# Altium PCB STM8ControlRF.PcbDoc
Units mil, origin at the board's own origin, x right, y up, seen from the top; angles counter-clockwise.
Board outline 2025.03 x 1260.03 mil, 2 copper layers (Top Layer, Bottom Layer); 18 components, 22 nets, 93 pads, 0 vias.
Unrouted connection lines stored in the file: 3.
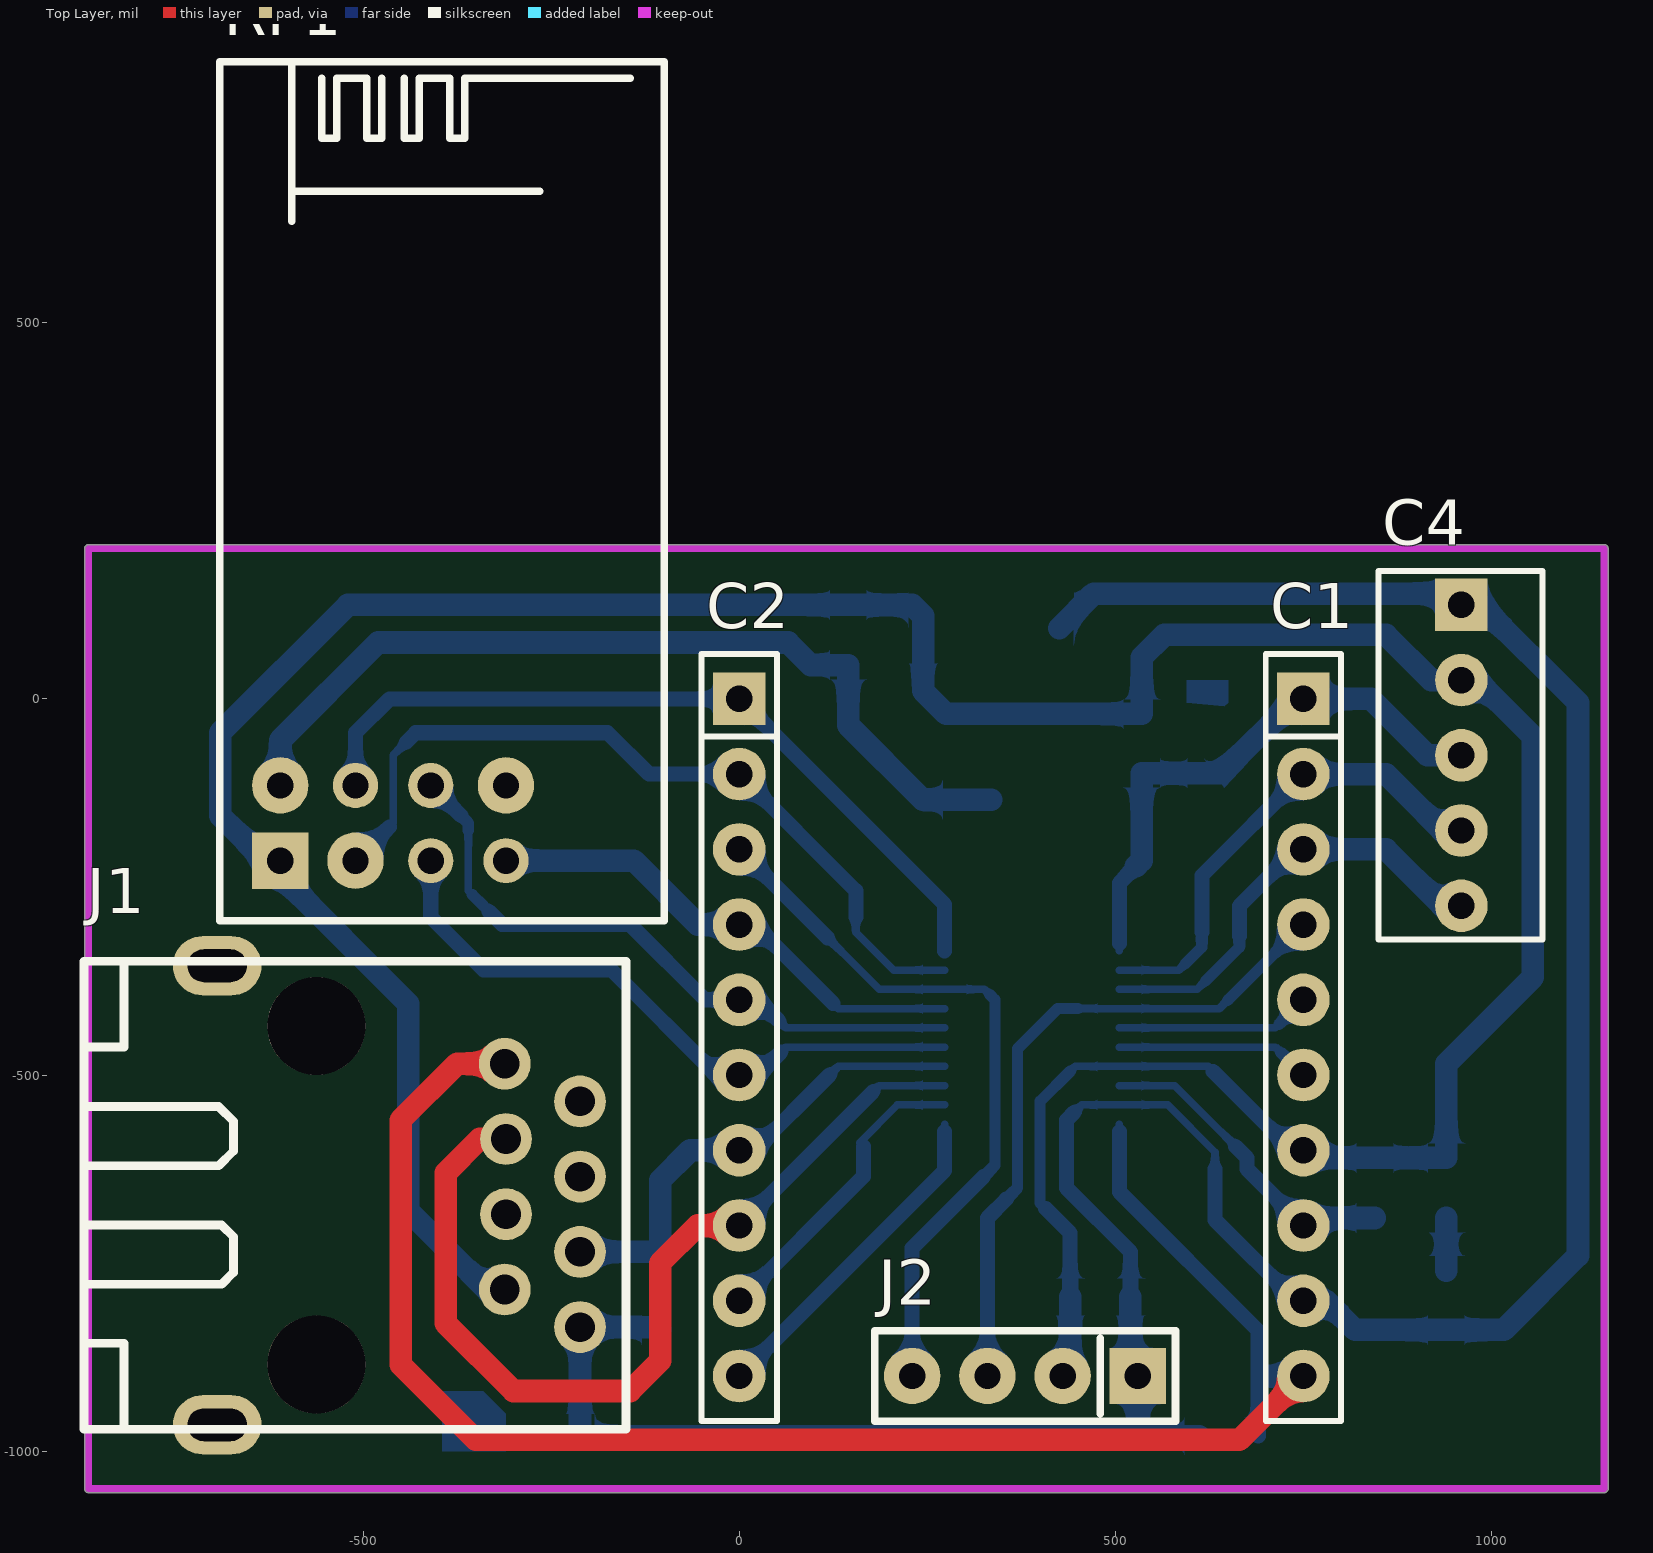
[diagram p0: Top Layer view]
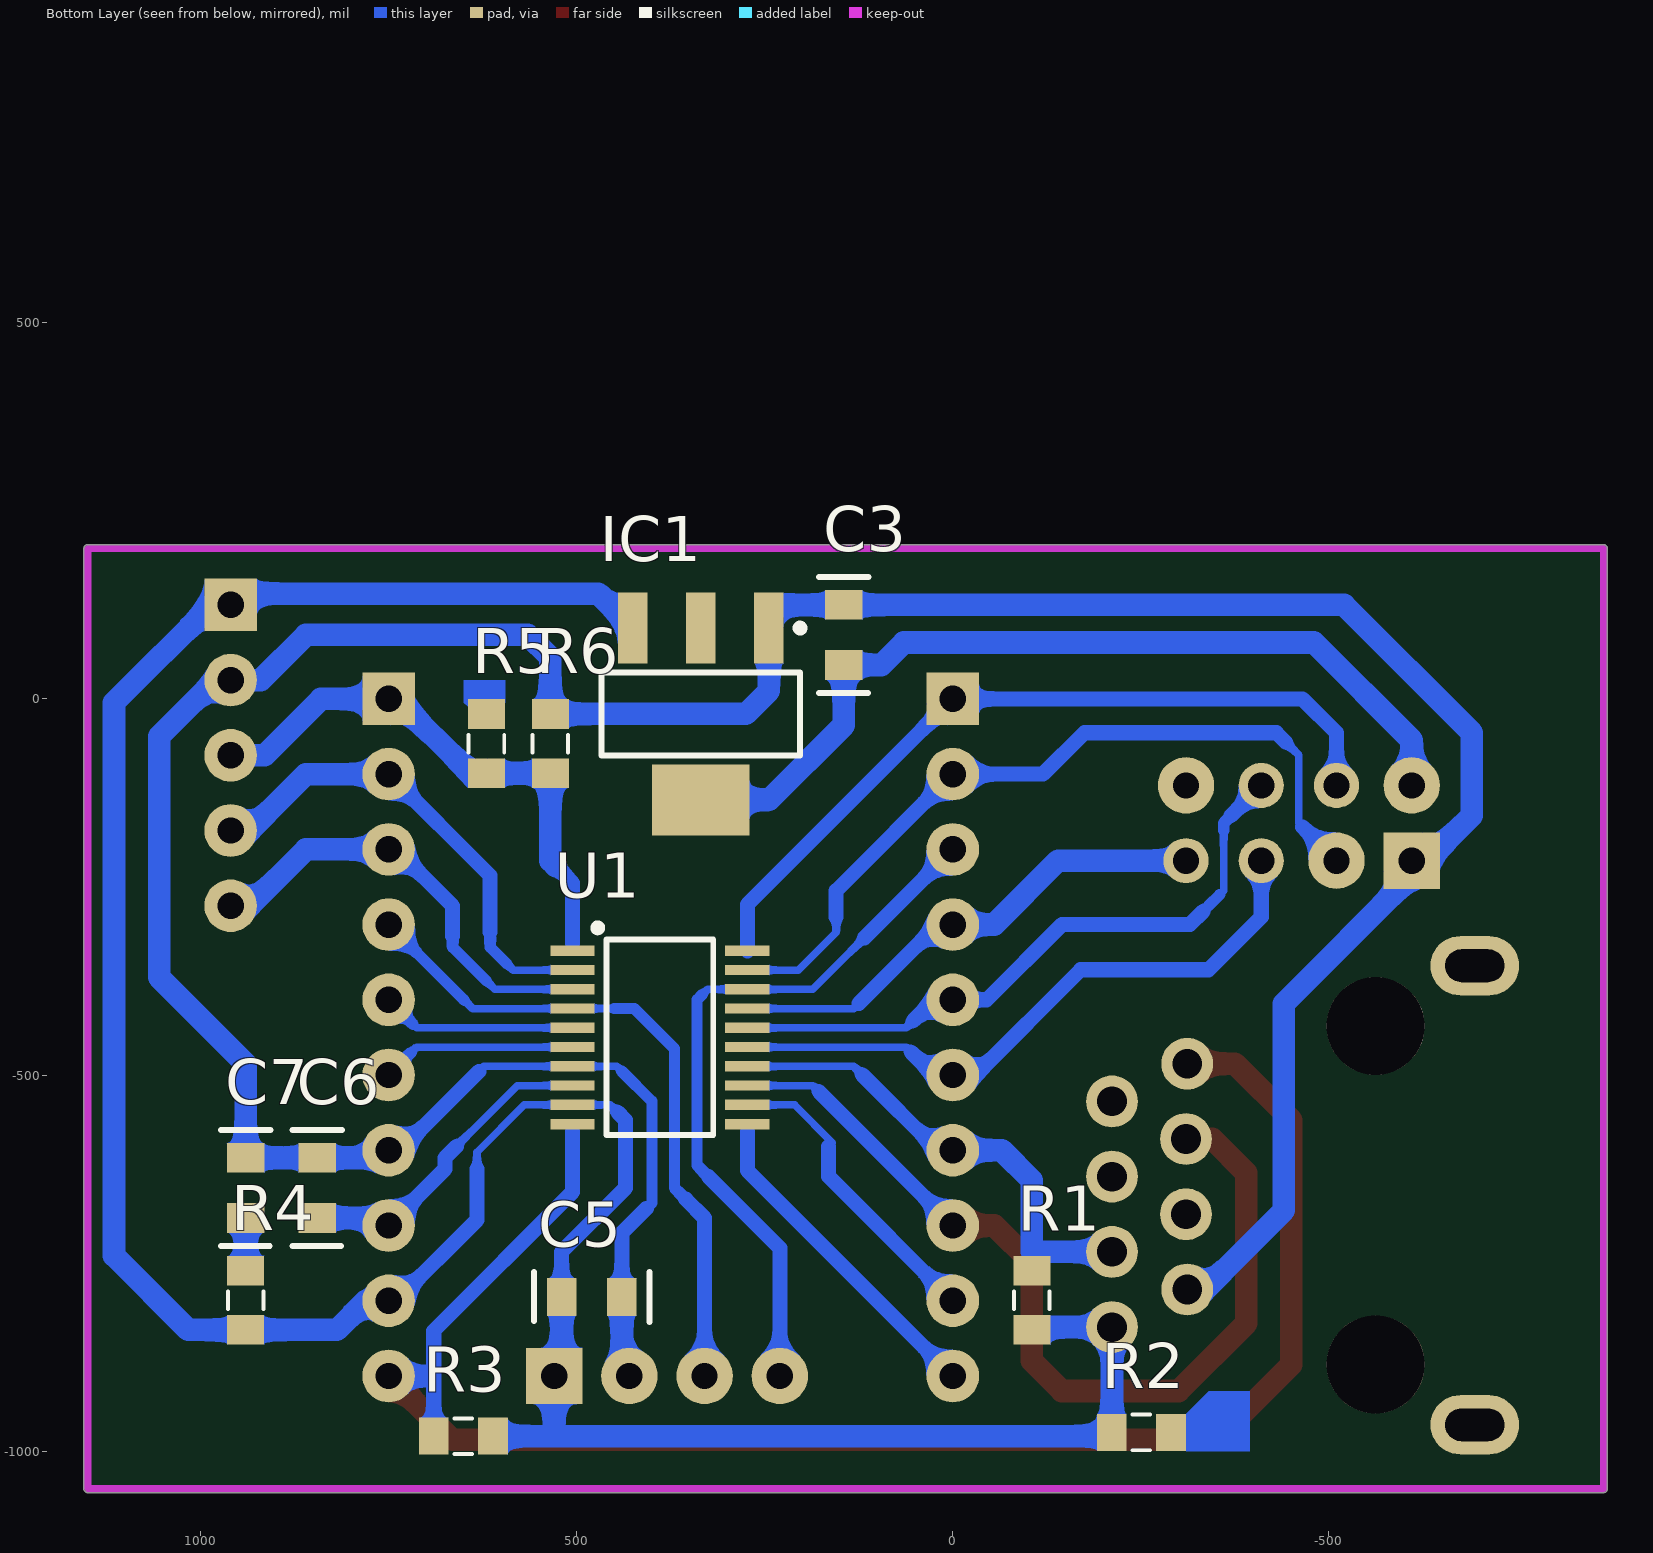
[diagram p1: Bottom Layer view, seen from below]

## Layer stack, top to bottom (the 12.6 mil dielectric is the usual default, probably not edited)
Top Solder: solder mask 0.4, Solder Resist, Dk 3.5
Top Layer: signal copper 1.4
Dielectric 1: dielectric 12.6, FR-4, Dk 4.8
Bottom Layer: signal copper 1.4
Bottom Solder: solder mask 0.4, Solder Resist, Dk 3.5

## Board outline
-865,-1055.01 cw(c-865,-1050) -870.02,-1050 -870.02,200 cw(c-865,200) -865,205.01 1150,205.01 cw(c1150,200) 1155.01,200 1155.01,-1050 cw(c1150,-1050) 1150,-1055.01

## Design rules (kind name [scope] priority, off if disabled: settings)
Clearance [All] p1: gap=10 ignorepadtopadclearanceinfootprint=FALSE except(0: Arc-Hole Track-Hole SMDPad-Hole THPad-Hole Via-Hole Fill-Hole Poly-Hole Region-Hole Text-Hole)
PolygonConnect [All] p1: connectstyle=Relief reliefconductorwidth=10 reliefentries=4 polygonreliefangle="90 Angle" airgapwidth=10
RoomDefinition STM8ControlRF [InComponentClass('STM8ControlRF')] p1: confinementstyle=ConfineIn formatcopy=TRUE lockcomponents=FALSE outline -2690,-3870 -690,-3870 -690,-2870 -2690,-2870
RoutingVias [All] p1: holewidth=28 width=50 viastyle="Through Hole" minholewidth=28 minwidth=50 maxholewidth=28 maxwidth=50
SolderMaskExpansion [All] p1: expansion=4
Width [All] p1: maxlimit=30 minlimit=10 preferedwidth=15
30 further rules are at their usual default settings.

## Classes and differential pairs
component class STM8ControlRF: C1 C2 C3 C4 C5 C6 C7 IC1 J1 J2 R1 R2 R4 R5 R6 RF1 U1

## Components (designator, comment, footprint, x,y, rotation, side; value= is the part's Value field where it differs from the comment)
C1 "JP10" JP10-C1T 750,0 r270 top
C2 "JP10" JP10-C1T 0,0 r270 top
C3 "104" C0805 145,85 r270 bottom value=33p
C4 "Header5" HDR5 960,125 r270 top
C5 "104" C0805 480,-795 r0 bottom value=33p
C6 "105" C0805 845,-650 r270 bottom value=33p
C7 "104" C0805 940,-650 r270 bottom value=33p
IC1 "AMS_1117" SOT_223_2 335,-20 r270 bottom
J1 "RJ45-12P" RJ45-8PIN_18MM_NO_TRANSFORMER -871.02,-659.8 r270 top
J2 "Jump_4" Jump_4 530,-900 r270 top
R1 "10K" RES-0805 -105,-760 r90 bottom value=1K
R2 "10K" RES-0805 -290,-975 r180 bottom value=1K
R3 "10K" RES-0805 690,-980 r0 bottom value=1K
R4 "10K" RES-0805 940,-760 r90 bottom value=1K
R5 "1K" RES-0805 620,-98.74 r270 bottom
R6 "2K" RES-0805 535,-20 r90 bottom value=1K
RF1 "RF24L01" RF24L01 -395,-95 r270 top
U1 "STM8S003F3P6" TSSOP20 389.37,-450 r180 bottom

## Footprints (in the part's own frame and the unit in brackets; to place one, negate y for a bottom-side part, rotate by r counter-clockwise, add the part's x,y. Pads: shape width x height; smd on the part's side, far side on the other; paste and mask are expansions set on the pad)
C0805 [mil] "Chip Resistor; Body 2.0 x 1.3 mm (LxW typ)"
  rect 39.37x50 smd: 1(-40,0) 2(40,0)
  silkscreen extent -77,-33 77,33, body extent -39,-25 39,25, height 31
HDR5 [mil] "Connector; Header; 5 Position"
  rect 70x70 hole 35: 1(0,0)
  round 70 hole 35: 2(100,0) 3(200,0) 4(300,0) 5(400,0)
  silkscreen extent -45,-110 445,108, body extent -50,-115 450,113, height 461
JP10-C1T [mil] "10 row, straight, gold plating"
  rect 70x70 hole 35: 1(0,0)
  round 70 hole 35: 2(100,0) 3(200,0) 4(300,0) 5(400,0) 6(500,0) 7(600,0) 8(700,0) 9(800,0) 10(900,0)
  silkscreen extent -60,-50 960,50, body extent -60,-49 960,49, height 335
Jump_4 [mil] "Jump_4 Pin 2.54"
  rect 75x75 hole 35: 1(0,0)
  round 75 hole 35: 2(0,-100) 3(0,-200) 4(0,-300)
  silkscreen extent -60,-350 60,50, body extent -53,-353 53,53, height 346
RES-0805 [mm] "Chip Resistor; Body 2 x 1.2 mm (LxW typ)"
  rect 1x1.25 smd: 1(0,0) 2(-2,0)
  silkscreen extent -1.3,-0.6 -0.7,0.6, body extent -2,-0.6 0,0.6, height 0.7
RF24L01 [mil] "Module RF24L01"
  rect 75x75 hole 35: 1(120,-215)
  round 75 hole 35: 2(20,-215) 3(120,-115) 8(20,85)
  round 60 hole 35: 4(20,-115) 5(120,-15) 6(20,-15) 7(120,85)
  silkscreen extent -942,-295 200,295, body extent -942,-300 200,290, height 138
RJ45-8PIN_18MM_NO_TRANSFORMER [mm]
  oval 2x3 hole 1.1 slot 2 at 90 deg mask+0: 0(-7.75,4.5) 0(7.75,4.5)
  round 3.3 hole 3.3 unplated mask+0: 0(-5.715,7.85) 0(5.715,7.85)
  round 1.75 hole 1: 1(-4.44,14.21) 2(-3.17,16.75) 3(-1.9,14.25) 4(-0.63,16.75) 5(0.64,14.25) 6(1.91,16.75) 7(3.18,14.21) 8(4.45,16.75)
  silkscreen extent -7.9,0 7.9,18.3, body extent -7.9,0 7.9,18.3, height 13.2
SOT_223_2 [mm] "SOT223, 4-Leads, Body 6.5x3.5mm, Pitch 2.3mm, Lead Span 7mm, IPC Medium Density"
  rect 2.4x1 smd: 1(-2.9,2.3) 2(-2.9,0) 3(-2.9,-2.3)
  rect 2.4x3.3 smd: 2(2.9,0)
  silkscreen extent -3.02,-3.35 1.4,3.47, body extent -3.39,-3.27 3.5,3.23, height 1.72
TSSOP20 [mm] "TSOP, 20-Leads, Body 6.5x4.4mm, Pitch 0.65mm, IPC Medium Density"
  rect 1.5x0.35 smd: 1(-2.95,2.925) 2(-2.95,2.275) 3(-2.95,1.625) 4(-2.95,0.975) 5(-2.95,0.325) 6(-2.95,-0.325) 7(-2.95,-0.975) 8(-2.95,-1.625) 9(-2.95,-2.275) 10(-2.95,-2.925) 11(2.95,-2.925) 12(2.95,-2.275) 13(2.95,-1.625) 14(2.95,-0.975) 15(2.95,-0.325) 16(2.95,0.325) 17(2.95,0.975) 18(2.95,1.625) 19(2.95,2.275) 20(2.95,2.925)
  silkscreen extent -2.23,-3.3 1.8,3.82, body extent -3.2,-3.25 3.2,3.25, height 1.2

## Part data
C1 C2: "WR-PHD 2.54 mm Angled Socket Header", Manufacturer="Würth Elektronik eiSos GmbH", partNo=613010143121
C3 C5 C6 C7: library part CapSMD, "Capacitor"
C4: "Header IDC, 5 x 1 Pin Vertical 2.54mm Pitch (Non-Boxed, Male)", Manufacturer="Würth Elektronik eiSos GmbH", partNo=613002143121
IC1: "IC Power"
J1: library part RJ45-12PIN_NO_TRANSFORMER
R1 R2 R3 R4 R5 R6: library part RES, "Resistor SMD"
RF1: "Module RF24L01"

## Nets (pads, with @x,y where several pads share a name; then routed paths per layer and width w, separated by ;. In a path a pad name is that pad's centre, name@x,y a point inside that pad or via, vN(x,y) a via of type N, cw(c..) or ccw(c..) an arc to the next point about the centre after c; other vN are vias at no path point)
1: C1.1 C4.3 R5.1 R6.2 U1.1 | length 745.3
  Bottom Layer w10: U1.1 505.51,-325
  Bottom Layer w20: 505.51,-325 505.51,-244.49 527.5,-222.5
  Bottom Layer w30: 527.5,-222.5 535,-215 R6.2 R5.1 641.26,-98.74 740,0 C1.1 840,0 915,-75 C4.3
2: C1.2 C4.4 U1.2 | length 649.1
  Bottom Layer w10: U1.2 584.57,-360.43 592.5,-352.5
  Bottom Layer w15: 592.5,-352.5 615,-330 615,-310
  Bottom Layer w20: 615,-310 615,-235 C1.2
  Bottom Layer w30: C1.2 860,-100 935,-175 C4.4
3: C1.3 C4.5 U1.3 | length 594.8
  Bottom Layer w10: U1.3 608.98,-386.02 620,-375
  Bottom Layer w15: 620,-375 665,-330 665,-315
  Bottom Layer w20: 665,-315 665,-275 740,-200 C1.3
  Bottom Layer w30: C1.3 860,-200 935,-275 C4.5
4: C1.4 J2.3 U1.4 | length 899.9
  Bottom Layer w10: 450,-411.61 U1.4 638.39,-411.61 650,-400
  Bottom Layer w15: 355,-665 370,-650 370,-465 423.39,-411.61 450,-411.61 ; 650,-400 C1.4
  Bottom Layer w20: J2.3 330,-690 355,-665
5: C1.5 U1.5 | length 259.9
  Bottom Layer w10: U1.5 712.8,-437.2 717.5,-432.5
  Bottom Layer w15: 717.5,-432.5 C1.5
6: C1.6 U1.6 | length 259.9
  Bottom Layer w10: U1.6 712.8,-462.8 720,-470
  Bottom Layer w15: 720,-470 C1.6
7: C1.7 C3.1 C4.2 C5.1 C6.1 C7.1 IC1.1 J1.7 J2.2 R6.1 RF1.1 U1.7 | length 4602.6
  Bottom Layer w10: 440,-495 446.61,-488.39 U1.7 623.39,-488.39 630,-495
  Bottom Layer w15: 407.5,-677.5 400,-670 400,-535 440,-495
  Bottom Layer w20: 407.5,-677.5 440,-710 C5.1 ; 630,-495 735,-600 C1.7
  Bottom Layer w30: J1.7 -335,-785 -440,-680 -440,-405 -610,-235 RF1.1 -630,-215 -690,-155 -690,-45 -520,125 C3.1 230,125 244.45,110.55 IC1.1 244.45,10.55 275,-20 R6.1 535,55 565,85 860,85 920,25 C4.2 980,25 1055,-50 1055,-370 940,-485 C7.1 C6.1 760,-610 C1.7 ; J2.2 440,-890 C5.1
8: C1.8 C6.2 U1.8 | length 429.5
  Bottom Layer w10: U1.8 578.98,-513.98 660,-595
  Bottom Layer w20: 660,-595 675,-610 675,-625 C1.8
  Bottom Layer w30: C1.8 760,-690 C6.2
10: C1.10 J1.1 R3.1 U1.10 | length 2317.4
  Top Layer w30: J1.1 -375,-485 -450,-560 -450,-885 -350,-985 665,-985 C1.10
  Bottom Layer w10: 505.51,-575 U1.10
  Bottom Layer w20: 505.51,-575 505.51,-655.51 690,-840 R3.1
  Bottom Layer w30: 695,-900 C1.10
11: C2.10 U1.11 | length 455.1
  Bottom Layer w10: 273.23,-575 U1.11
  Bottom Layer w20: C2.10 273.23,-626.77 273.23,-575
  Bottom Layer w30: C2.10@-5,-895 C2.10
12: C2.9 U1.12 | length 407.5
  Bottom Layer w10: 160,-590 210.43,-539.57 U1.12
  Bottom Layer w20: C2.9 165,-635 165,-595
13: C2.8 J1.3 R2.1 U1.13 | length 1243.5
  Top Layer w30: J1.3 -345,-585 -390,-630 -390,-830 -300,-920 -145,-920 -105,-880 -105,-750 -55,-700 C2.8
  Bottom Layer w10: 177.5,-522.5 186.02,-513.98 U1.13
  Bottom Layer w20: C2.8 177.5,-522.5
14: C2.7 J1.6 R1.1 U1.14 | length 642.6
  Bottom Layer w10: 120,-500 131.61,-488.39 U1.14
  Bottom Layer w20: C2.7 20,-600 120,-500
  Bottom Layer w30: J1.6 -105,-735 -105,-640 -65,-600 C2.7
15: C2.6 RF1.5 U1.15 | length 860.6
  Bottom Layer w10: 55,-470 62.2,-462.8 U1.15
  Bottom Layer w20: RF1.5 -410,-290 -340,-360 -170,-360 -30,-500 C2.6 25,-500 55,-470
16: C2.5 RF1.6 U1.16 | length 869.4
  Bottom Layer w10: -360,-175 -360,-255 -355,-260 ; -340,-275 -332.5,-282.5 ; 52.5,-427.5 62.2,-437.2 U1.16
  Bottom Layer w15: -370,-155 -360,-165 -360,-175 ; -355,-260 -340,-275
  Bottom Layer w20: RF1.6 -370,-155 ; -332.5,-282.5 -315,-300 -145,-300 -45,-400 C2.5 25,-400 52.5,-427.5
17: C2.4 RF1.7 U1.17 | length 664.7
  Bottom Layer w10: 125,-405 131.61,-411.61 U1.17
  Bottom Layer w20: C2.4 20,-300 125,-405
  Bottom Layer w30: RF1.7 -140,-215 -55,-300 C2.4
18: C2.3 J2.4 U1.18 | length 968.4
  Bottom Layer w10: 117.5,-317.5 186.02,-386.02 U1.18 326.02,-386.02 333.01,-393.01
  Bottom Layer w15: 325,-635 340,-620 340,-400 333.01,-393.01
  Bottom Layer w20: C2.3 117.5,-317.5 ; J2.4 230,-730 325,-635
19: C2.2 RF1.3 U1.19 | length 1069.2
  Bottom Layer w10: -465,-170 -460,-165 -460,-75 -442.5,-57.5 ; 155,-290 155,-310 205.43,-360.43 U1.19
  Bottom Layer w20: RF1.3 -465,-170 ; -442.5,-57.5 -430,-45 -175,-45 -120,-100 C2.2 155,-255 155,-290
20: C2.1 RF1.4 U1.20 | length 1046.7
  Bottom Layer w20: RF1.4 -510,-45 -465,0 C2.1 273.23,-273.23 273.23,-325 U1.20
+3V3: C3.2 IC1.2 RF1.2 | length 1192.4
  Bottom Layer w30: RF1.2 -610,-55 -480,75 65,75 95,45 C3.2 145,-35 244.17,-134.17 IC1.2@335,-134.17
+5V: C1.9 C4.1 C5.2 IC1.3 J1.8 J2.1 R1.2 R2.2 R3.2 R4.2 R5.2 U1.9 | length 3954.4
  Bottom Layer w10: 445.22,-549.78 455.43,-539.57 U1.9 569.57,-539.57 632.5,-602.5 632.5,-625
  Bottom Layer w20: 445.22,-549.78 435,-560 435,-650 520,-735 C5.2 ; 632.5,-625 632.5,-692.5 740,-800 C1.9
  Bottom Layer w30: R1.2 -108.74,-835 J1.8 R2.2@-211.57,-974.68 ; IC1.3 471.38,140 945,140 C4.1 985,125 1115,-5 1115,-740 1016.26,-838.74 R4.2 818.74,-838.74 780,-800 C1.9 ; C5.2 520,-890 J2.1 530,-975 525,-980 ; R3.2 525,-980 ; R2.2@-211.57,-974.68 -211.57,-980 R2.2@-206.26,-980 ; R2.2@-211.57,-974.68 R2.2 R2.2@-206.26,-980 ; R2.2@-206.26,-980 -15,-980 415,-980 525,-980
NRST: C7.2 R4.1 | length 70
  Bottom Layer w30: R4.1 C7.2
pads on no net: J1.0 J1.2 J1.4 J1.5 RF1.8

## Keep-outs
Keep-Out Layer:
  lines w10: -865,-1050 -865,200 -500,200 1150,200 1150,-1050 -865,-1050

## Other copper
Bottom Layer:
  region net +5V: 595,-5 595,25 650,25 650,-5 645,-10
  region: 595,0
  region: -310,-950 -340,-920 -395,-920 -395,-1000 -310,-1000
